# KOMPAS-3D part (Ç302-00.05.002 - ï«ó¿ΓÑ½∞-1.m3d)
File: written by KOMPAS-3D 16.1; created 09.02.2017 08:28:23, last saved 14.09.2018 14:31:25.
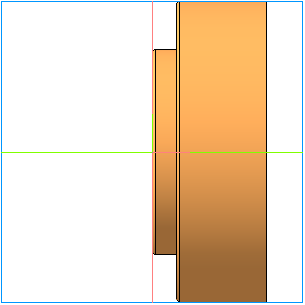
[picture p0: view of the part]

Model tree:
1. Эскиз:24
2. Операция вращения:2
     Угол 1 = 360
3. Фаска:1  (labels: Фторопласт-4  ГОСТ 10007-80 Е)
     Угол = 45; Длина 1 = 0.5; Длина 2 = 0.5

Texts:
  Линейный размер с обрывом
